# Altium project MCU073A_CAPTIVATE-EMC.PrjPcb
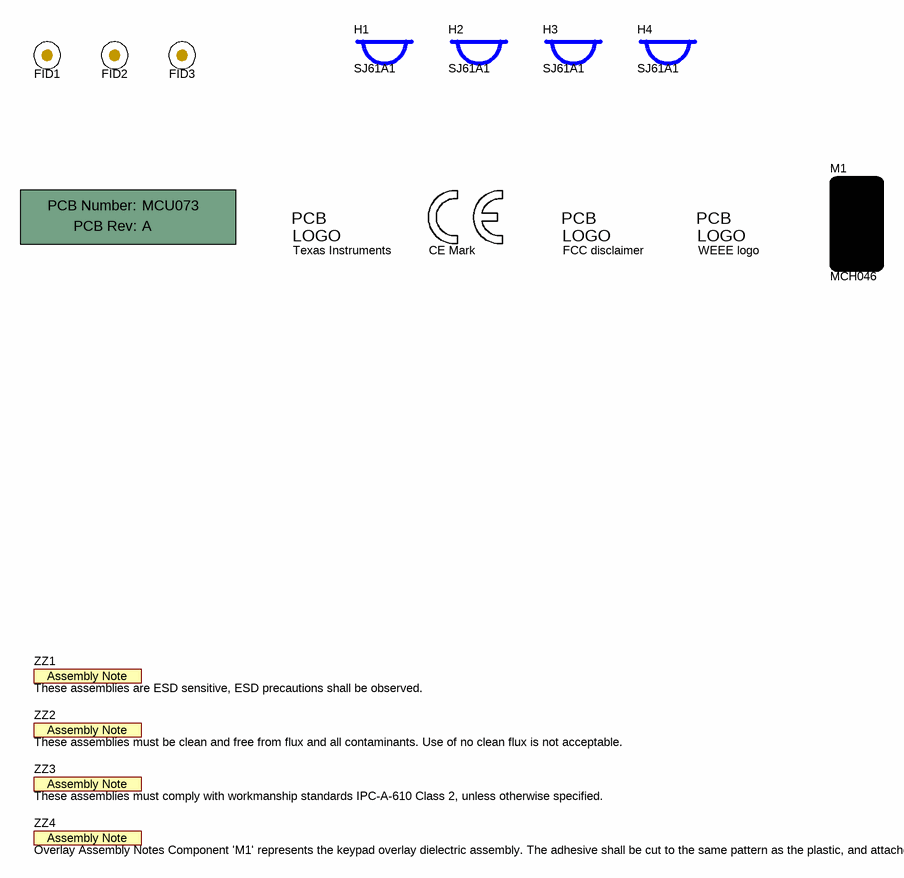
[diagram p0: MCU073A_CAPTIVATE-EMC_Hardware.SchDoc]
CopyrightYear: 2019; PCB_Layout: Ling Zhu; PCB_Rev: A; PRJ_Customer: Public Release; PRJ_Engineer: Ling Zhu; PRJ_Number: MCU073; PRJ_Title: CAPTIVATE-EMC; SCH_Rev: A; TechSupport: http://www.ti.com/support; TID: N/A
3 sheets, 127 parts. Net scope: global (net labels, ports and power ports of the same name join across sheets).
Board file: MCU073A_CAPTIVATE-EMC.PcbDoc
Sheets:
  MCU073A_CAPTIVATE-EMC_Hardware.SchDoc
  MCU073A_CAPTIVATE-EMC_MCU.SchDoc
  MCU073A_CAPTIVATE-EMC_PowerSupply.SchDoc

## Sheet MCU073A_CAPTIVATE-EMC_Hardware.SchDoc: CAPTIVATE-EMC_Hardware
size 431 x 279 mm; Date: Not shown in title block; ApprovedBy: Not shown in title block; CheckedBy: Not shown in title block; Author: Not shown in title block; CompanyName: Not shown in title block; DrawnBy: Ling Zhu; Engineer: Not shown in title block; Organization: Not shown in title block; Address1: Not shown in title block; Address2: Not shown in title block; Address3: Not shown in title block; Address4: Not shown in title block; DocumentNumber: 3; Revision: Use project parameter SCH_Rev; SheetNumber: 3; SheetTotal: 3; PageSetup: Record=PageOptions¦CenterHorizontal=True¦CenterVertical=True¦PrintScale=1.00¦XCorrection=1.00¦YCorrection=1.00¦PrintKind=0¦BorderSize=5000000¦LeftOffset=0¦BottomOffset=0¦Orientation=2¦PaperLength=1000¦PaperWidth=1000¦Scale=100¦PaperSource=15¦PrintQuality=600¦MediaType=1¦DitherType=10¦PaperKind=Letter¦PrintScaleMode=1

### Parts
!PCB1  Printed Circuit Board  (value not drawn)  (mechanical)
FID1  Fiducial  [Fiducial10-20]  (value not drawn)
FID2  Fiducial  [Fiducial10-20]  (value not drawn)
FID3  Fiducial  [Fiducial10-20]  (value not drawn)
H1  SJ61A1  [Bumpon_SJ61A1]
H2  SJ61A1  [Bumpon_SJ61A1]
H3  SJ61A1  [Bumpon_SJ61A1]
H4  SJ61A1  [Bumpon_SJ61A1]
Logo1  CE Mark  [CE_Mark_5mm]  (no BOM)
Logo2  Texas Instruments  [TI_Stacked_Overlay_Small]  (no BOM)
Logo3  FCC disclaimer  [FCC_disclaimer]  (no BOM)
Logo4  WEEE logo  [WEEE_Minimum]  (no BOM)
M1  MCH046  [CAPTIVATE-EMC-OVERLAY-PMMA]
ZZ1  These assemblies are ESD sensitive, ESD precautions shall be observed.  [AssemblyNote]  (no BOM)
ZZ2  These assemblies must be clean and free from flux and all contaminants. Use of no clean flux is not acceptable.  [AssemblyNote]  (no BOM)
ZZ3  These assemblies must comply with workmanship standards IPC-A-610 Class 2, unless otherwise specified.  [AssemblyNote]  (no BOM)
ZZ4  Overlay Assembly Notes / Component 'M1' represents the keypad overlay dielectric assembly. / The adhesive shall be cut to the same pattern as the plastic, and attached to the back of the plastic.  Then, the overlay plastic shall be bonded to the top layer of the PCB.  [AssemblyNote]  (no BOM)

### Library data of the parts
!PCB1 = CMP-0003618-2: Manufacturer: Any; PartNumber: MCU073
FID1-FID3 = CMP-0077181-1: Fiducial mark.  There is nothing to buy or mount.
H1-H4 = CMP-0003621-1: Bumpon, Cylindrical, 0.312 X 0.200, Black; Manufacturer: 3M
Logo1 = CMP-0074844-1: SymbolCreator: a0412235
Logo2 = CMP-0074838-1: Texas Instrument Corporate Signature; SymbolCreator: a0412235; Lib Reference: TI_Logo; Library Reference: Logo
Logo3 = CMP-0074847-1: FCC_disclaimer; Library Reference: Logo
Logo4 = CMP-0074769-1
M1 = CAPTIVATE-EMC-OVERLAY-PMMA: CAPTIVATE-EMC Overlay Plastic; Manufacturer: ANY; SymbolCreator: a0222632; CompType: Mechanical; U/M: EA, IN, or GM
ZZ1 = CMP-0077236-1
ZZ2 = CMP-0077237-1
ZZ3 ZZ4 = CMP-0077238-1

## Sheet MCU073A_CAPTIVATE-EMC_MCU.SchDoc: CAPTIVATE-EMC_MCU
size 431 x 279 mm; Date: Not shown in title block; ApprovedBy: Not shown in title block; CheckedBy: Not shown in title block; Author: Not shown in title block; CompanyName: Not shown in title block; DrawnBy: Ling Zhu; Engineer: Not shown in title block; Organization: Not shown in title block; Address1: Not shown in title block; Address2: Not shown in title block; Address3: Not shown in title block; Address4: Not shown in title block; DocumentNumber: 1; Revision: Use project parameter SCH_Rev; SheetNumber: 1; SheetTotal: 3; PageSetup: Record=PageOptions¦CenterHorizontal=True¦CenterVertical=True¦PrintScale=1.00¦XCorrection=1.00¦YCorrection=1.00¦PrintKind=0¦BorderSize=5000000¦LeftOffset=0¦BottomOffset=0¦Orientation=2¦PaperLength=1000¦PaperWidth=1000¦Scale=100¦PaperSource=15¦PrintQuality=600¦MediaType=1¦DitherType=10¦PaperKind=Letter¦PrintScaleMode=1
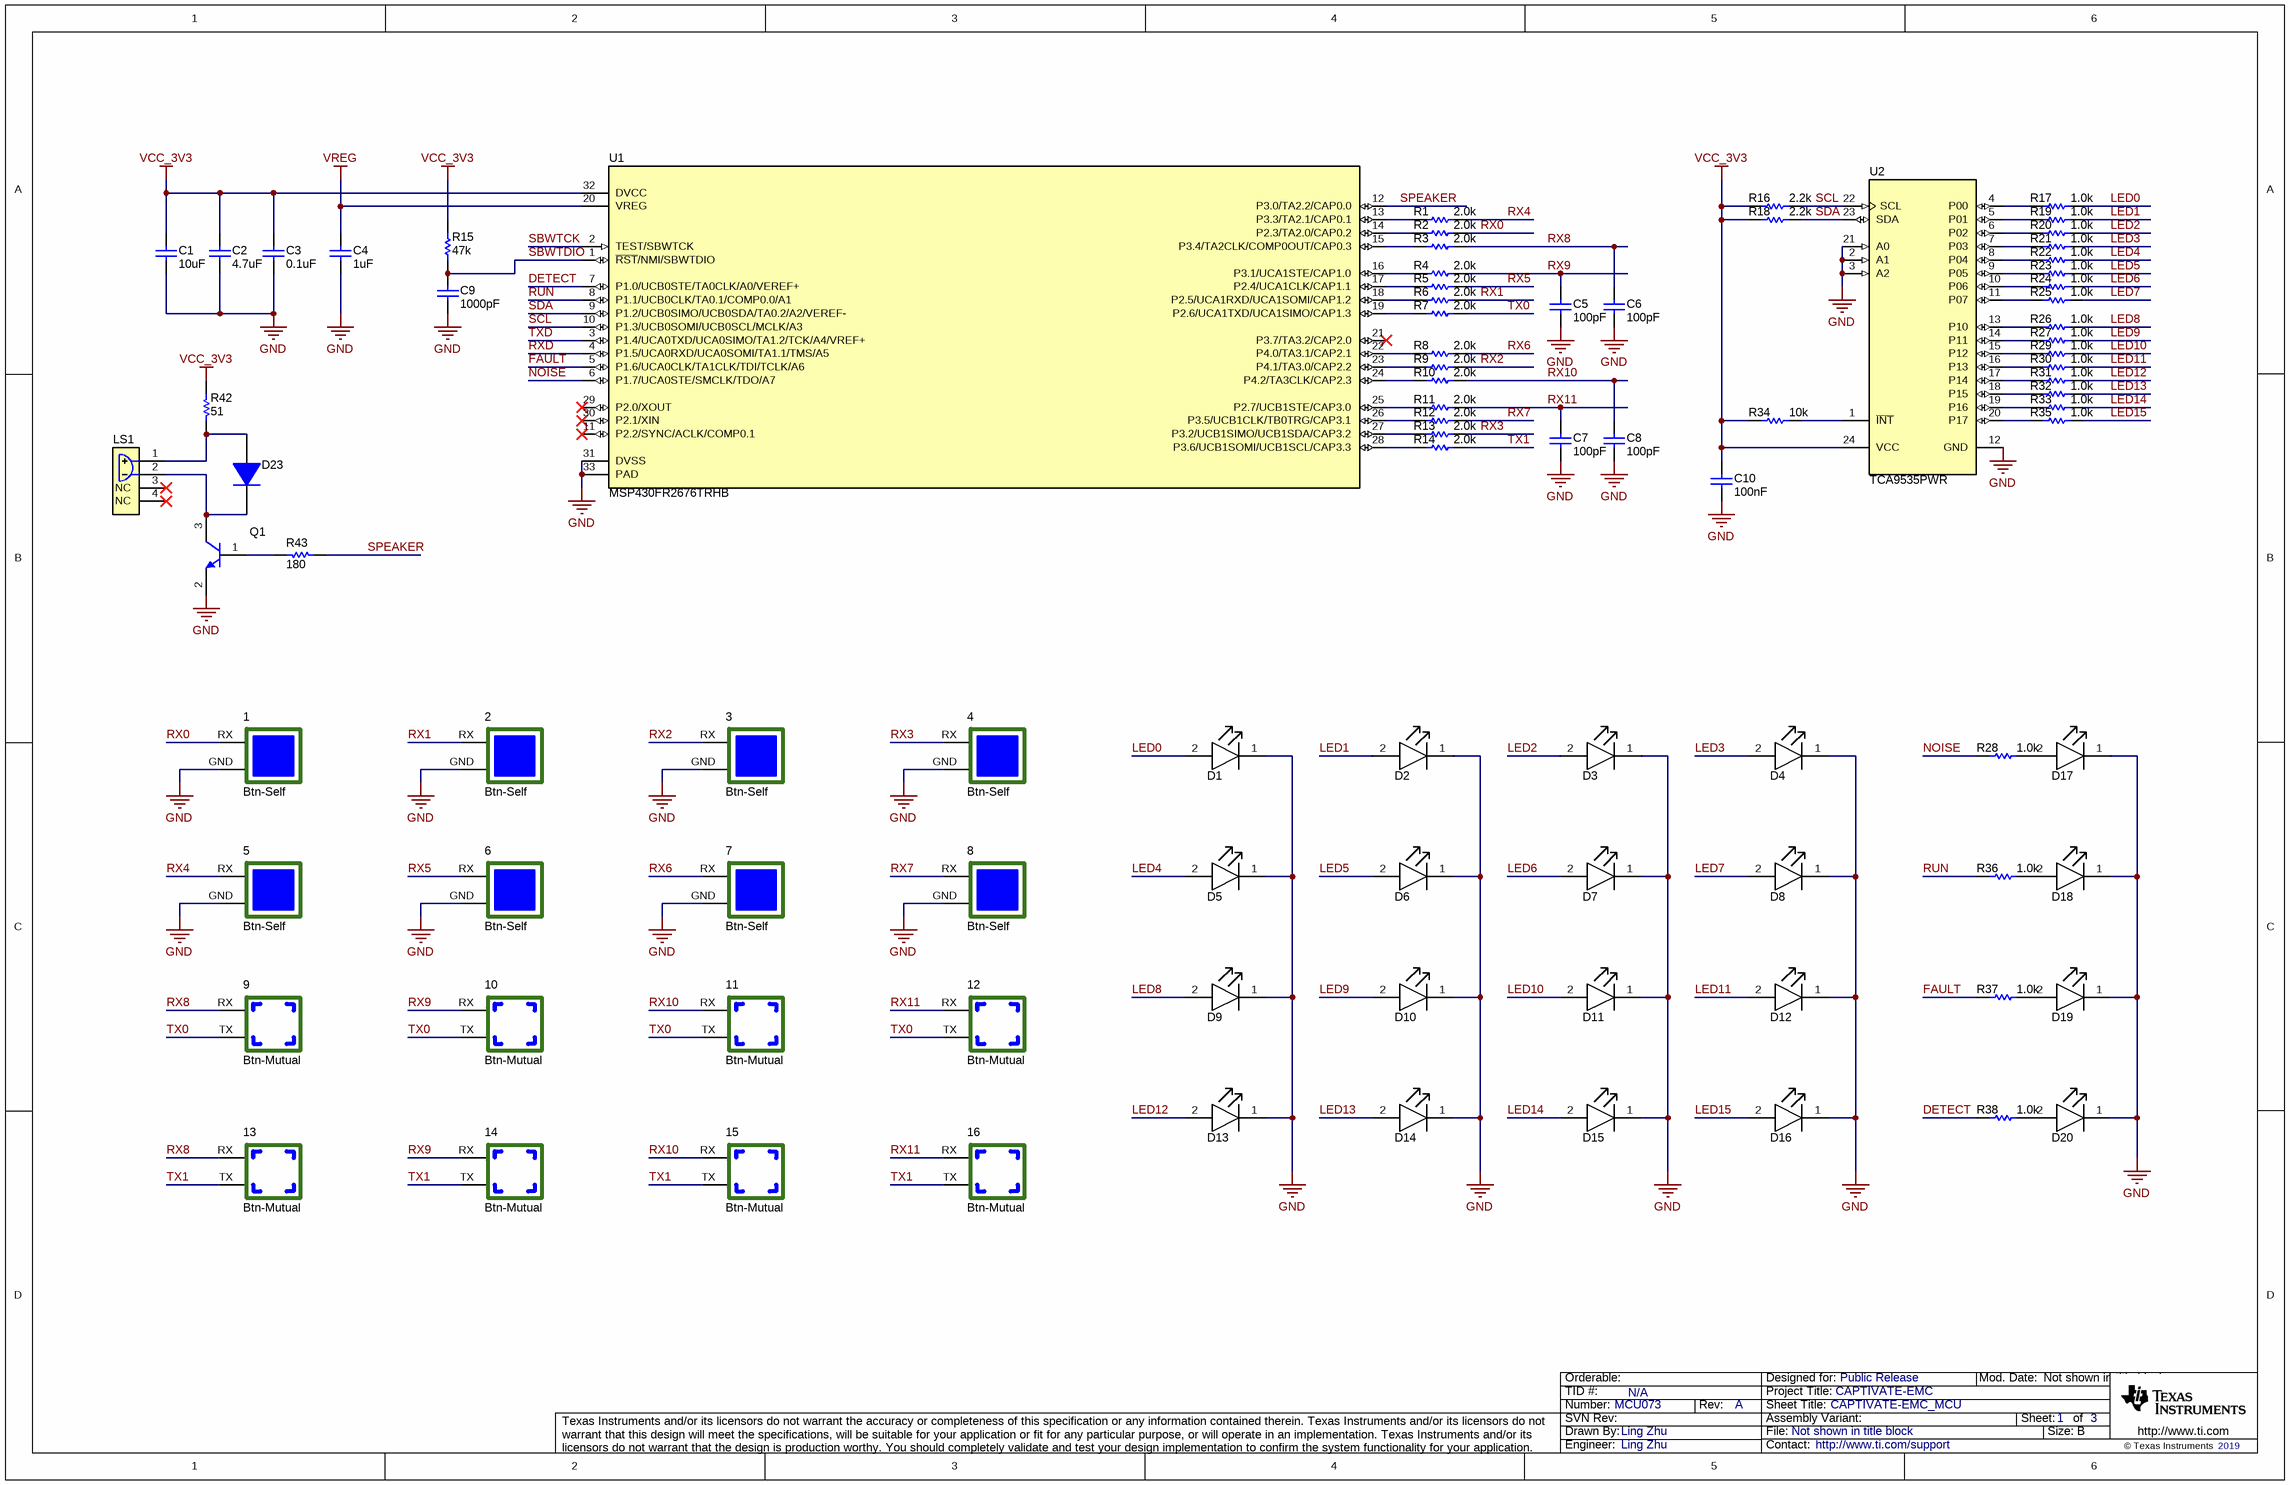
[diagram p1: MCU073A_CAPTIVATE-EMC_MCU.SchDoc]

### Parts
1  Btn-Self  [btn-self]  (no BOM)
2  Btn-Self  [btn-self]  (no BOM)
3  Btn-Self  [btn-self]  (no BOM)
4  Btn-Self  [btn-self]  (no BOM)
5  Btn-Self  [btn-self]  (no BOM)
6  Btn-Self  [btn-self]  (no BOM)
7  Btn-Self  [btn-self]  (no BOM)
8  Btn-Self  [btn-self]  (no BOM)
9  Btn-Mutual  [btn-mutual]  (no BOM)
10  Btn-Mutual  [btn-mutual]  (no BOM)
11  Btn-Mutual  [btn-mutual]  (no BOM)
12  Btn-Mutual  [btn-mutual]  (no BOM)
13  Btn-Mutual  [btn-mutual]  (no BOM)
14  Btn-Mutual  [btn-mutual]  (no BOM)
15  Btn-Mutual  [btn-mutual]  (no BOM)
16  Btn-Mutual  [btn-mutual]  (no BOM)
C1  ValueDisplayed: 10uF  [0603]  (hidden comment: GRM188R60J106ME47D)
C2  ValueDisplayed: 4.7uF  [0402]  (hidden comment: C1005X5R0J475M050BC)
C3  ValueDisplayed: 0.1uF  [0402]  (hidden comment: GCM155R71C104KA55D)
C4  ValueDisplayed: 1uF  [0402]  (hidden comment: GRM155R70J105KA12D)
C5  ValueDisplayed: 100pF  [0402]  (hidden comment: C0402C101J3GACTU)
C6  ValueDisplayed: 100pF  [0402]  (hidden comment: C0402C101J3GACTU)
C7  ValueDisplayed: 100pF  [0402]  (hidden comment: C0402C101J3GACTU)
C8  ValueDisplayed: 100pF  [0402]  (hidden comment: C0402C101J3GACTU)
C9  ValueDisplayed: 1000pF  [0402]  (hidden comment: GCM155R71H102KA37D)
C10  Cap_F: 100nF  [0603]  (hidden comment: GCJ188R72A104KA01D)
D1  AM2520SRC09  [FP-AM2520SRC09_SMD2-MFG]  (value not drawn)
D2  AM2520SRC09  [FP-AM2520SRC09_SMD2-MFG]  (value not drawn)
D3  AM2520SRC09  [FP-AM2520SRC09_SMD2-MFG]  (value not drawn)
D4  AM2520SRC09  [FP-AM2520SRC09_SMD2-MFG]  (value not drawn)
D5  AM2520SRC09  [FP-AM2520SRC09_SMD2-MFG]  (value not drawn)
D6  AM2520SRC09  [FP-AM2520SRC09_SMD2-MFG]  (value not drawn)
D7  AM2520SRC09  [FP-AM2520SRC09_SMD2-MFG]  (value not drawn)
D8  AM2520SRC09  [FP-AM2520SRC09_SMD2-MFG]  (value not drawn)
D9  AM2520SRC09  [FP-AM2520SRC09_SMD2-MFG]  (value not drawn)
D10  AM2520SRC09  [FP-AM2520SRC09_SMD2-MFG]  (value not drawn)
D11  AM2520SRC09  [FP-AM2520SRC09_SMD2-MFG]  (value not drawn)
D12  AM2520SRC09  [FP-AM2520SRC09_SMD2-MFG]  (value not drawn)
D13  AM2520SRC09  [FP-AM2520SRC09_SMD2-MFG]  (value not drawn)
D14  AM2520SRC09  [FP-AM2520SRC09_SMD2-MFG]  (value not drawn)
D15  AM2520SRC09  [FP-AM2520SRC09_SMD2-MFG]  (value not drawn)
D16  AM2520SRC09  [FP-AM2520SRC09_SMD2-MFG]  (value not drawn)
D17  AM2520SECK09  [FP-AM2520SECK09_SMT_LED_2MM5_2MM0-MFG]  (value not drawn)
D18  AM2520ZGC09  [FP-AM2520ZGC09_SMD2-0]  (value not drawn)
D19  AM2520SRC09  [FP-AM2520SRC09_SMD2-MFG]  (value not drawn)
D20  AM2520QBC/D09  [FP-AM2520QBC_D09]  (value not drawn)
D23  1N4148WX-TP  [SOD-323]  (value not drawn)
LS1  ST-03BL  [Soberton_ST-03BL]  (value not drawn)
Q1  MMBT3904-7-F  [SOT-23]  (value not drawn)
R1  ValueDisplayed: 2.0k  [0402]  (hidden comment: CRCW04022K00JNED)
R2  ValueDisplayed: 2.0k  [0402]  (hidden comment: CRCW04022K00JNED)
R3  ValueDisplayed: 2.0k  [0402]  (hidden comment: CRCW04022K00JNED)
R4  ValueDisplayed: 2.0k  [0402]  (hidden comment: CRCW04022K00JNED)
R5  ValueDisplayed: 2.0k  [0402]  (hidden comment: CRCW04022K00JNED)
R6  ValueDisplayed: 2.0k  [0402]  (hidden comment: CRCW04022K00JNED)
R7  ValueDisplayed: 2.0k  [0402]  (hidden comment: CRCW04022K00JNED)
R8  ValueDisplayed: 2.0k  [0402]  (hidden comment: CRCW04022K00JNED)
R9  ValueDisplayed: 2.0k  [0402]  (hidden comment: CRCW04022K00JNED)
R10  ValueDisplayed: 2.0k  [0402]  (hidden comment: CRCW04022K00JNED)
R11  ValueDisplayed: 2.0k  [0402]  (hidden comment: CRCW04022K00JNED)
R12  ValueDisplayed: 2.0k  [0402]  (hidden comment: CRCW04022K00JNED)
R13  ValueDisplayed: 2.0k  [0402]  (hidden comment: CRCW04022K00JNED)
R14  ValueDisplayed: 2.0k  [0402]  (hidden comment: CRCW04022K00JNED)
R15  ValueDisplayed: 47k  [0402]  (hidden comment: CRCW040247K0JNED)
R16  ValueDisplayed: 2.2k  [0402]  (hidden comment: CRCW04022K20JNED)
R17  ValueDisplayed: 1.0k  [0402]  (hidden comment: CRCW04021K00JNED)
R18  ValueDisplayed: 2.2k  [0402]  (hidden comment: CRCW04022K20JNED)
R19  ValueDisplayed: 1.0k  [0402]  (hidden comment: CRCW04021K00JNED)
R20  ValueDisplayed: 1.0k  [0402]  (hidden comment: CRCW04021K00JNED)
R21  ValueDisplayed: 1.0k  [0402]  (hidden comment: CRCW04021K00JNED)
R22  ValueDisplayed: 1.0k  [0402]  (hidden comment: CRCW04021K00JNED)
R23  ValueDisplayed: 1.0k  [0402]  (hidden comment: CRCW04021K00JNED)
R24  ValueDisplayed: 1.0k  [0402]  (hidden comment: CRCW04021K00JNED)
R25  ValueDisplayed: 1.0k  [0402]  (hidden comment: CRCW04021K00JNED)
R26  ValueDisplayed: 1.0k  [0402]  (hidden comment: CRCW04021K00JNED)
R27  ValueDisplayed: 1.0k  [0402]  (hidden comment: CRCW04021K00JNED)
R28  ValueDisplayed: 1.0k  [0402]  (hidden comment: CRCW04021K00JNED)
R29  ValueDisplayed: 1.0k  [0402]  (hidden comment: CRCW04021K00JNED)
R30  ValueDisplayed: 1.0k  [0402]  (hidden comment: CRCW04021K00JNED)
R31  ValueDisplayed: 1.0k  [0402]  (hidden comment: CRCW04021K00JNED)
R32  ValueDisplayed: 1.0k  [0402]  (hidden comment: CRCW04021K00JNED)
R33  ValueDisplayed: 1.0k  [0402]  (hidden comment: CRCW04021K00JNED)
R34  ValueDisplayed: 10k  [0603]  (hidden comment: RC1608J103CS)
R35  ValueDisplayed: 1.0k  [0402]  (hidden comment: CRCW04021K00JNED)
R36  ValueDisplayed: 1.0k  [0402]  (hidden comment: CRCW04021K00JNED)
R37  ValueDisplayed: 1.0k  [0402]  (hidden comment: CRCW04021K00JNED)
R38  ValueDisplayed: 1.0k  [0402]  (hidden comment: CRCW04021K00JNED)
R42  ValueDisplayed: 51  [0402]  (hidden comment: CRCW040251R0JNED)
R43  ValueDisplayed: 180  [0402]  (hidden comment: CRCW0402180RJNED)
U1  MSP430FR2676TRHB  [RHB0032E]
U2  TCA9535PWR  [PW0024A_N]

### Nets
GND: 1.GND 2.GND 3.GND 4.GND 5.GND 6.GND 7.GND 8.GND C1.2 C2.2 C3.1 C4.2 C5.1 C6.1 C7.1 C8.1 C9.1 C10.2 D1.1(CATHODE) D2.1(CATHODE) D3.1(CATHODE) D4.1(CATHODE) D5.1(CATHODE) D6.1(CATHODE) D7.1(CATHODE) D8.1(CATHODE) D9.1(CATHODE) D10.1(CATHODE) D11.1(CATHODE) D12.1(CATHODE) D13.1(CATHODE) D14.1(CATHODE) D15.1(CATHODE) D16.1(CATHODE) D17.1(CATHODE) D18.1(CATHODE) D19.1(CATHODE) D20.1(CATHODE) Q1.2(E) U1.31(DVSS) U1.33(PAD) U2.2(A1) U2.3(A2) U2.12(GND) U2.21(A0)
VCC_3V3: C1.1 C2.1 C3.2 C10.1 R15.2 R16.2 R18.2 R34.1 R42.2 U1.32(DVCC) U2.24(VCC)
VREG: C4.1 U1.20(VREG)
DETECT: R38.1 U1.7(P1.0/UCB0STE/TA0CLK/A0/VEREF+)
FAULT: R37.1 U1.5(P1.6/UCA0CLK/TA1CLK/TDI/TCLK/A6)
LED0: D1.2(ANODE) R17.2
LED1: D2.2(ANODE) R19.2
LED2: D3.2(ANODE) R20.2
LED3: D4.2(ANODE) R21.2
LED4: D5.2(ANODE) R22.2
LED5: D6.2(ANODE) R23.2
LED6: D7.2(ANODE) R24.2
LED7: D8.2(ANODE) R25.2
LED8: D9.2(ANODE) R26.2
LED9: D10.2(ANODE) R27.2
LED10: D11.2(ANODE) R29.2
LED11: D12.2(ANODE) R30.2
LED12: D13.2(ANODE) R31.2
LED13: D14.2(ANODE) R32.2
LED14: D15.2(ANODE) R33.2
LED15: D16.2(ANODE) R35.2
NOISE: R28.1 U1.6(P1.7/UCA0STE/SMCLK/TDO/A7)
RUN: R36.1 U1.8(P1.1/UCB0CLK/TA0.1/COMP0.0/A1)
RX0: 1.RX R2.2
RX1: 2.RX R6.2
RX2: 3.RX R9.2
RX3: 4.RX R13.2
RX4: 5.RX R1.2
RX5: 6.RX R5.2
RX6: 7.RX R8.2
RX7: 8.RX R12.2
RX8: 9.RX 13.RX C6.2 R3.2
RX9: 10.RX 14.RX C5.2 R4.2
RX10: 11.RX 15.RX C8.2 R10.2
RX11: 12.RX 16.RX C7.2 R11.2
RXD: U1.4(P1.5/UCA0RXD/UCA0SOMI/TA1.1/TMS/A5)
SBWTCK: U1.2(TEST/SBWTCK)
SBWTDIO: C9.2 R15.1 U1.1(~{RST}/NMI/SBWTDIO)
SCL: R16.1 U1.10(P1.3/UCB0SOMI/UCB0SCL/MCLK/A3) U2.22(SCL)
SDA: R18.1 U1.9(P1.2/UCB0SIMO/UCB0SDA/TA0.2/A2/VEREF-) U2.23(SDA)
SPEAKER: R43.1 U1.12(P3.0/TA2.2/CAP0.0)
TX0: 9.TX 10.TX 11.TX 12.TX R7.2
TX1: 13.TX 14.TX 15.TX 16.TX R14.2
TXD: U1.3(P1.4/UCA0TXD/UCA0SIMO/TA1.2/TCK/A4/VREF+)
NetD17_2: D17.2(ANODE) R28.2
NetD18_2: D18.2(ANODE) R36.2
NetD19_2: D19.2(ANODE) R37.2
NetD20_2: D20.2(ANODE) R38.2
NetD23_1: D23.1(K) LS1.2(-) Q1.3(C)
NetD23_2: D23.2(A) LS1.1(+) R42.1
NetQ1_1: Q1.1(B) R43.2
NetR1_1: R1.1 U1.13(P3.3/TA2.1/CAP0.1)
NetR2_1: R2.1 U1.14(P2.3/TA2.0/CAP0.2)
NetR3_1: R3.1 U1.15(P3.4/TA2CLK/COMP0OUT/CAP0.3)
NetR4_1: R4.1 U1.16(P3.1/UCA1STE/CAP1.0)
NetR5_1: R5.1 U1.17(P2.4/UCA1CLK/CAP1.1)
NetR6_1: R6.1 U1.18(P2.5/UCA1RXD/UCA1SOMI/CAP1.2)
NetR7_1: R7.1 U1.19(P2.6/UCA1TXD/UCA1SIMO/CAP1.3)
NetR8_1: R8.1 U1.22(P4.0/TA3.1/CAP2.1)
NetR9_1: R9.1 U1.23(P4.1/TA3.0/CAP2.2)
NetR10_1: R10.1 U1.24(P4.2/TA3CLK/CAP2.3)
NetR11_1: R11.1 U1.25(P2.7/UCB1STE/CAP3.0)
NetR12_1: R12.1 U1.26(P3.5/UCB1CLK/TB0TRG/CAP3.1)
NetR13_1: R13.1 U1.27(P3.2/UCB1SIMO/UCB1SDA/CAP3.2)
NetR14_1: R14.1 U1.28(P3.6/UCB1SOMI/UCB1SCL/CAP3.3)
NetR17_1: R17.1 U2.4(P00)
NetR19_1: R19.1 U2.5(P01)
NetR20_1: R20.1 U2.6(P02)
NetR21_1: R21.1 U2.7(P03)
NetR22_1: R22.1 U2.8(P04)
NetR23_1: R23.1 U2.9(P05)
NetR24_1: R24.1 U2.10(P06)
NetR25_1: R25.1 U2.11(P07)
NetR26_1: R26.1 U2.13(P10)
NetR27_1: R27.1 U2.14(P11)
NetR29_1: R29.1 U2.15(P12)
NetR30_1: R30.1 U2.16(P13)
NetR31_1: R31.1 U2.17(P14)
NetR32_1: R32.1 U2.18(P15)
NetR33_1: R33.1 U2.19(P16)
NetR34_2: R34.2 U2.1(~{INT})
NetR35_1: R35.1 U2.20(P17)

Not connected (* = marked no-connect by the designer): LS1 3(NC)* 4(NC)*; U1 11(P2.2/SYNC/ACLK/COMP0.1)* 21(P3.7/TA3.2/CAP2.0)* 29(P2.0/XOUT)* 30(P2.1/XIN)*

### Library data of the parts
1-8 = btn-self: Capacitive Button, Self Capacitance, 2-Layer, EMC; SymbolCreator: a0222632; CompType: Electrode; U/M: EA, IN, or GM
9-16 = btn-mutual: Capacitive Button, Mutual Capacitance, 2-layer; SymbolCreator: a0222632; CompType: Electrode; U/M: EA, IN, or GM
C1 = CMP-0007303-5: CAP, CERM, 10 uF, 6.3 V, +/- 20%, X5R, 0603; Manufacturer: MuRata; TaMin_C: -55°C; ESR_ohm: 9m; Polarized: N; SizeAreaWB_mm2: 4.68; Value1: 0.009 ohm; U/M: EA; Value: 10uF; TaMax_C: 125°C; SizeZ_mm: 1; SizeX_mm: 1.6; SizeY_mm: 0.8; Value2: 6.3V; SizeArea_mm2: 1.28; Cap_F: 10µF; IRMS_A: 2.74A; AEC Category: Q200
C2 = CMP-0006258-2: CAP, CERM, 4.7 uF, 6.3 V, +/- 20%, X5R, 0402; Manufacturer: TDK; TaMin_C: -55°C; Polarized: N; SizeAreaWB_mm2: 3; Value1: Unknown; U/M: EA; Value: 4.7uF; TaMax_C: 85°C; SizeZ_mm: 0.6; SizeX_mm: 1; SizeY_mm: 0.5; Value2: 6.3V; Cap_F: 4.7µF; AEC Category: Q200
C3 = CMP-0006351-2: CAP, CERM, 0.1 uF, 16 V, +/- 10%, X7R, 0402; Manufacturer: MuRata; TaMin_C: -55°C; Polarized: N; SizeAreaWB_mm2: 3; Value1: Unknown; U/M: EA; Value: 0.1uF; TaMax_C: 125°C; SizeZ_mm: 0.6; SizeX_mm: 1; SizeY_mm: 0.5; Value2: 16V; Cap_F: 100nF; AEC Category: Q200
C4 = CMP-0064947-2: CAP, CERM, 1 uF, 6.3 V,+/- 10%, X7R, 0402; Manufacturer: MuRata; TaMin_C: -55°C; Polarized: N; SizeAreaWB_mm2: 3; Value1: Unknown; U/M: EA; Value: 1uF; TaMax_C: 125°C; SizeZ_mm: 0.6; SizeX_mm: 1; SizeY_mm: 0.5; Value2: 6.3V; Cap_F: 1µF; AEC Category: Q200
C5-C8 = CMP-0006233-2: CAP, CERM, 100 pF, 25 V, +/- 5%, C0G/NP0, 0402; Manufacturer: Kemet; TaMin_C: -55°C; Polarized: N; SizeAreaWB_mm2: 3; Value1: Unknown; U/M: EA; Value: 100pF; TaMax_C: 125°C; SizeZ_mm: 0.6; SizeX_mm: 1; SizeY_mm: 0.5; Value2: 25V; AEC Category: Q200
C9 = CMP-0006354-2: CAP, CERM, 1000 pF, 50 V, +/- 10%, X7R, AEC-Q200 Grade 1, 0402; Manufacturer: MuRata; TaMin_C: -55°C; Polarized: N; SizeAreaWB_mm2: 3; Value1: Unknown; U/M: EA; Value: 1000pF; TaMax_C: 125°C; SizeZ_mm: 0.6; SizeX_mm: 1; SizeY_mm: 0.5; Value2: 50V; AEC Qualified: Y; Cap_F: 1nF; AEC Category: Q200
C10 = CMP-0064935-4: CAP, CERM, 0.1 uF, 100 V,+/- 10%, X7R, AEC-Q200 Grade 1, 0603; Manufacturer: MuRata; TaMin_C: -55°C; Polarized: N; SizeAreaWB_mm2: 4.68; Value1: Unknown; U/M: EA; Value: 0.1uF; TaMax_C: 125°C; SizeZ_mm: 1; SizeX_mm: 1.6; SizeY_mm: 0.8; Value2: 100V; SizeArea_mm2: 1.28; AEC Qualified: Y; AEC Category: Q200
D1-D16 D19 = CMP-0086387-1: Red 2.5 x 2 x 2.8 mm 20° Clear 800 mcd 1.85 V Subminiature Solid State LED SMT; Manufacturer: Kingbright Company LLC; SizeZ_mm: 1.7mm; LambdaD: 640nm; Vr_V: 5V; Symbol Name: SYM-AM2520SRC09; Power_TotalModule: 75mW; Vf_V: 1.85V; LambdaP: 655nm
D17 = CMP-0086381-1: SUBMINIATURE SOLID STATE LAMP, Super Bright Orange, 20º, 2700mcd Clear; Manufacturer: Kingbright; Vf_V: 2.1V; Vr_V: 5V; Symbol Name: SYM-AM2520SECK09; Tjmax_C: 115°C; Angle: 20°; LambdaD: 605nm; SizeZ_mm: 1.5mm; LambdaP: 610nm; Power_TotalModule: 75mW
D18 = CMP-0087006-1: Green 2.5 x 2 x 2.8 mm 20° Clear 2700 mcd 3.3 V Subminiature Solid State LED SMT; Manufacturer: Kingbright; Power_TotalModule: 102.5mW; LambdaD: 525nm; SizeZ_mm: 1.7mm; Symbol Name: SYM-AM2520ZGC09; LambdaP: 515nm; Vf_V: 3.3V; Vr_V: 5V; Tjmax_C: 115°C
D20 = CMP-0077505-2: LED Blue 465nm - Discrete 3.3V 2-SMD, Z-Bend; Manufacturer: Kingbright; Power_TotalModule: 120mW; LambdaP: 460nm; SizeZ_mm: 1.7mm; Angle: 20°; Symbol Name: SYM-AM2520QBC/D09; Tjmax_C: 115°C; Vr_V: 5V
D23 = CMP-0082069-2: Diode, Switching, 75 V, 0.15 A, SOD-323; Manufacturer: Micro Commercial Components; AEC Category: Q101; AEC Qualified: N; Value1: 0.15A; SizeX_mm: 2.7; Vr_V: 75V; Vf_V: 1V; SizeZ_mm: 1; SizeY_mm: 1.35; Value: 75V; SizeAreaWB_mm2: 8.695; TJmax_C: 150°C; RJC_CperW: 625; Io_A: 1.5dA; SizeArea_mm2: 3.645
LS1 = CMP-0078858-2: Magnetic Transducer, SMD; Manufacturer: Sobertron; SizeAreaWB_mm2: 110.25; SizeArea_mm2: 72.25; SizeZ_mm: 3.2; SizeX_mm: 8.5
Q1 = CMP-0000387-2: Transistor, NPN, 40 V, 0.2 A, SOT-23; Manufacturer: Diodes Inc.; TaMax_C: 150°C; Value2: 400; Value1: 0.2 A; Vcesat1_V: 200mV; SizeX_mm: 2.5; SizeY_mm: 3; TaMin_C: -55°C; IcRated_A: 200mA; CompType: BJT; SizeZ_mm: 1.1; Value: 40 V; SizeArea_mm2: 7.5; NPN: 1; Vceo_V: 40V; PNP: 0; AEC Category: Q101; SizeAreaWB_mm2: 14; U/M: EA
R1-R14 = CMP-0026889-5: RES, 2.0 k, 5%, 0.063 W, AEC-Q200 Grade 0, 0402; Manufacturer: Vishay-Dale; Power_W: 63mW; TempCo: 200 ppm/C; Value_Code: 2k00; Value: 2.0k; EIA_Code: E24; Res_ohm: 2k; SizeX_mm: 1; SizeY_mm: 0.5; SizeZ_mm: 0.6; Value2: 0.063W; AEC Qualified: Y; VDC_V: 50V; AEC Category: Q200; AEC Grade: 0
R15 = CMP-0026935-3: RES, 47 k, 5%, 0.063 W, AEC-Q200 Grade 0, 0402; Manufacturer: Vishay-Dale; Power_W: 63mW; TempCo: 200 ppm/C; Value_Code: 47k0; Value: 47k; EIA_Code: E24; SizeX_mm: 1; SizeY_mm: 0.5; SizeZ_mm: 0.6; Value2: 0.063W; AEC Qualified: Y; VDC_V: 50V; AEC Category: Q200; AEC Grade: 0
R16 R18 = CMP-0026890-5: RES, 2.2 k, 5%, 0.063 W, AEC-Q200 Grade 0, 0402; Manufacturer: Vishay-Dale; Power_W: 63mW; TempCo: 200 ppm/C; Value_Code: 2k20; Value: 2.2k; EIA_Code: E24; SizeX_mm: 1; SizeY_mm: 0.5; SizeZ_mm: 0.6; Value2: 0.063W; AEC Qualified: Y; VDC_V: 50V; AEC Category: Q200; AEC Grade: 0
R17 R19-R33 R35-R38 = CMP-0026852-3: RES, 1.0 k, 5%, 0.063 W, AEC-Q200 Grade 0, 0402; Manufacturer: Vishay-Dale; Power_W: 63mW; TempCo: 200 ppm/C; Value_Code: 1k00; Value: 1.0k; EIA_Code: E24; Res_ohm: 1k; SizeX_mm: 1; SizeY_mm: 0.5; SizeZ_mm: 0.6; Value2: 0.063W; AEC Qualified: Y; VDC_V: 50V; AEC Category: Q200; AEC Grade: 0
R34 = CMP-0025945-3: RES, 10 k, 5%, 0.1 W, 0603; Manufacturer: Samsung Electro-Mechanics; Power_W: 100mW; TempCo: 100 ppm/C; Value_Code: 10k0; U/M: EA; Value: 10k; EIA_Code: E24; SizeX_mm: 1.6; SizeY_mm: 0.8; SizeZ_mm: 1; Value2: 0.1W; SizeArea_mm2: 1.28; AEC Qualified: N; VDC_V: 31V; AEC Category: Q200
R42 = CMP-0026946-3: RES, 51, 5%, 0.063 W, AEC-Q200 Grade 0, 0402; Manufacturer: Vishay-Dale; Power_W: 63mW; TempCo: 200 ppm/C; Value_Code: 51R0; Value: 51; EIA_Code: E24; SizeX_mm: 1; SizeY_mm: 0.5; SizeZ_mm: 0.6; Value2: 0.063W; AEC Qualified: Y; VDC_V: 50V; AEC Category: Q200; AEC Grade: 0
R43 = CMP-0026849-3: RES, 180, 5%, 0.063 W, AEC-Q200 Grade 0, 0402; Manufacturer: Vishay-Dale; Power_W: 63mW; TempCo: 200 ppm/C; Value_Code: 180R; Value: 180; EIA_Code: E24; SizeX_mm: 1; SizeY_mm: 0.5; SizeZ_mm: 0.6; Value2: 0.063W; AEC Qualified: Y; VDC_V: 50V; AEC Category: Q200; AEC Grade: 0
U1 = CMP-0080656-1: Capacitive Touch Sensing Mixed-Signal Microcontroller, RHB0032E (VQFN-32); Manufacturer: Texas Instruments; SizeAreaWB_mm2: 49; SizeArea_mm2: 25; AEC Qualified: N; AEC Category: Q200; SizeZ_mm: 1; SizeY_mm: 5; CompType: IC
U2 = CMP-0043216-2: Remote 16-Bit I2C and SMBus, Low-Power I/O Expander With Interrupt Output and Config Registers, PW0024A (TSSOP-24); Manufacturer: Texas Instruments; SubFamily: I2C IO Expander; Vcc range(V): 1.65 to 5.5; Configuration Registers: Yes; Max Frequency(kHz): 400; Eco-Plan: Green (RoHS & no Sb/Br); # of I/Os: 16; I2C Address: 0100 xxx; Rating: Catalog; AEC Category: Q200; AEC Qualified: N; CompType: IC; SizeAreaWB_mm2: 82.32; SizeArea_mm2: 49.92; SizeX_mm: 6.4; SizeY_mm: 7.8; SizeZ_mm: 1.2

## Sheet MCU073A_CAPTIVATE-EMC_PowerSupply.SchDoc: CAPTIVATE-EMC_PowerSupply
size 431 x 279 mm; Date: Not shown in title block; ApprovedBy: Not shown in title block; CheckedBy: Not shown in title block; Author: Not shown in title block; CompanyName: Not shown in title block; DrawnBy: Ling Zhu; Engineer: Not shown in title block; Organization: Not shown in title block; Address1: Not shown in title block; Address2: Not shown in title block; Address3: Not shown in title block; Address4: Not shown in title block; DocumentNumber: 2; Revision: Use project parameter SCH_Rev; SheetNumber: 2; SheetTotal: 3; PageSetup: Record=PageOptions¦CenterHorizontal=True¦CenterVertical=True¦PrintScale=1.00¦XCorrection=1.00¦YCorrection=1.00¦PrintKind=0¦BorderSize=5000000¦LeftOffset=0¦BottomOffset=0¦Orientation=2¦PaperLength=1000¦PaperWidth=1000¦Scale=100¦PaperSource=15¦PrintQuality=600¦MediaType=1¦DitherType=10¦PaperKind=Letter¦PrintScaleMode=1
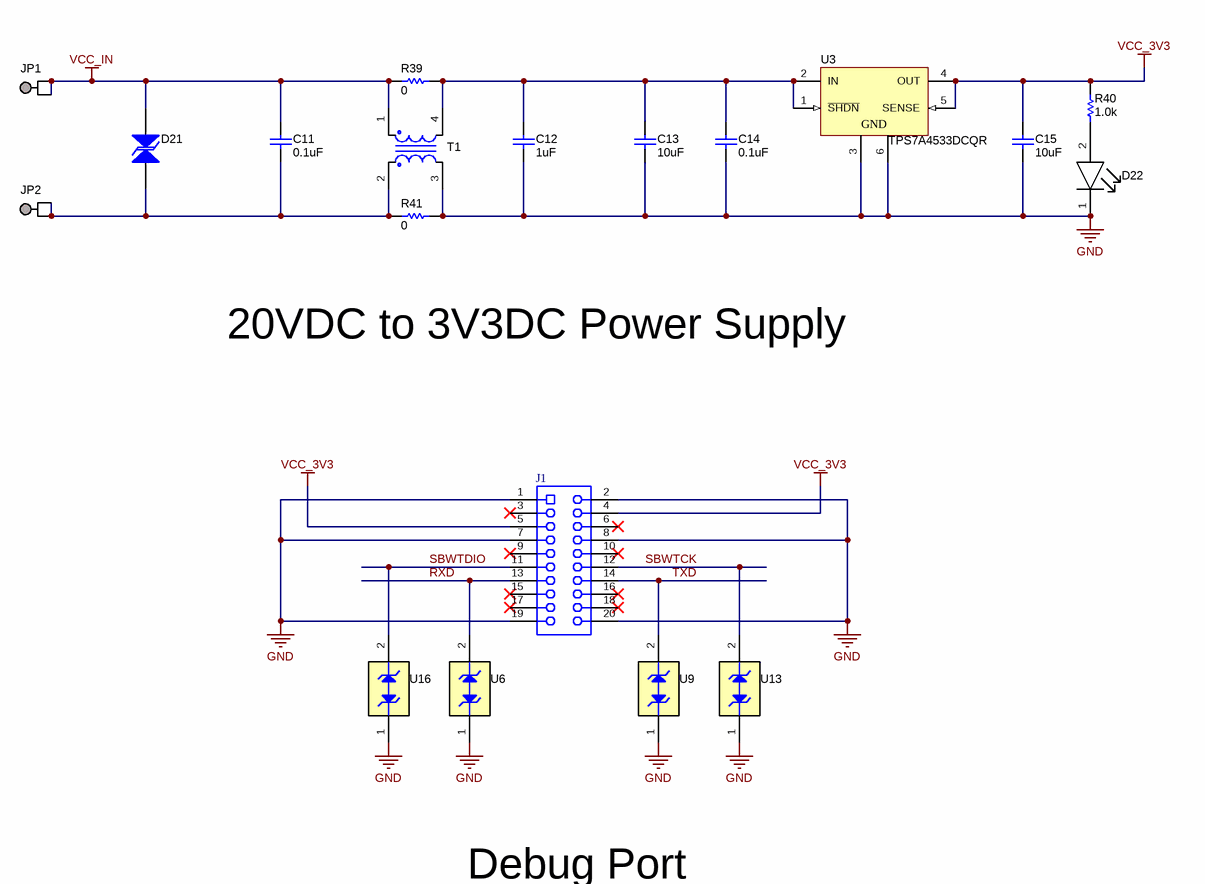
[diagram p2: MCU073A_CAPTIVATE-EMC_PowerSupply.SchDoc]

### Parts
C11  ValueDisplayed: 0.1uF  [1206]  (hidden comment: 12061C104MAT2A)
C12  ValueDisplayed: 1uF  [1206]  (hidden comment: 12063C105KAT2A)
C13  ValueDisplayed: 10uF  [0805_HV]  (hidden comment: CL21A106KAFN3NE)
C14  ValueDisplayed: 0.1uF  [0805_HV]  (hidden comment: 08053C104KAT2A)
C15  ValueDisplayed: 10uF  [0805_HV]  (hidden comment: CL21A106KAFN3NE)
D21  CDSOD323-T15SC  [SOD-323-Bi]  (value not drawn)
D22  AM2520SRC09  [FP-AM2520SRC09_SMD2-MFG]  (value not drawn)
J1  PPPC102LJBN-RC  [Sullins_xPxC102LJBN]  (value not drawn)
JP1  973 582-101  [HIRSCHMANN_973 582-101]  (value not drawn)
JP2  973 582-100  [HIRSCHMANN_973 582-100]  (value not drawn)
R39  ValueDisplayed: 0  [1206]  (hidden comment: MCR18EZHJ000)
R40  ValueDisplayed: 1.0k  [0402]  (hidden comment: CRCW04021K00JNED)
R41  ValueDisplayed: 0  [1206]  (hidden comment: MCR18EZHJ000)
T1  SRF0905-472Y  [SRF0905]  (value not drawn)
U3  TPS7A4533DCQR  [DCQ0006A_N]
U6  TPD1E10B06DPYT  [DPY0002A]  (value not drawn)
U9  TPD1E10B06DPYT  [DPY0002A]  (value not drawn)
U13  TPD1E10B06DPYT  [DPY0002A]  (value not drawn)
U16  TPD1E10B06DPYT  [DPY0002A]  (value not drawn)

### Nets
GND: C12.2 C13.2 C14.2 C15.2 D22.1(CATHODE) J1.1 J1.2 J1.7 J1.8 J1.19 J1.20 R41.2 T1.3 U3.3(GND) U3.6(GND) U6.1(K) U9.1(K) U13.1(K) U16.1(K)
VCC_3V3: C15.1 J1.4 J1.5 R40.2 U3.4(OUT) U3.5(SENSE)
VCC_IN: C11.2 D21.2 JP1.1 JP1.2 R39.1 T1.1
RXD: J1.13 U6.2(A)
SBWTCK: J1.12 U13.2(A)
SBWTDIO: J1.11 U16.2(A)
TXD: J1.14 U9.2(A)
NetC11_1: C11.1 D21.1 JP2.1 JP2.2 R41.1 T1.2
NetC12_1: C12.1 C13.1 C14.1 R39.2 T1.4 U3.1(~{SHDN}) U3.2(IN)
NetD22_2: D22.2(ANODE) R40.1

Not connected (* = marked no-connect by the designer): J1 3* 6* 9* 10* 15* 16* 17* 18*

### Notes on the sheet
- 20VDC to 3V3DC Power Supply
- Debug Port

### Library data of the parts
C11 = CMP-0008489-2: CAP, CERM, 0.1 uF, 100 V, +/- 20%, X7R, 1206; Manufacturer: AVX; TaMin_C: -55°C; ESR_ohm: 0.037; Polarized: N; SizeAreaWB_mm2: 10.92; Value1: 0.037 ohm; U/M: EA; Value: 0.1uF; TaMax_C: 125°C; SizeZ_mm: 1.35; SizeX_mm: 3.2; SizeY_mm: 1.6; Value2: 100V; SizeArea_mm2: 5.12; CompType: Capacitor; Cap_F: 100nF; AEC Category: Q200
C12 = CMP-0008509-2: CAP, CERM, 1 uF, 25 V, +/- 10%, X7R, 1206; Manufacturer: AVX; TaMin_C: -55°C; ESR_ohm: 0.013; Polarized: N; SizeAreaWB_mm2: 10.92; Value1: 0.013 ohm; U/M: EA; Value: 1uF; TaMax_C: 125°C; SizeZ_mm: 1.35; SizeX_mm: 3.2; SizeY_mm: 1.6; Value2: 25V; SizeArea_mm2: 5.12; CompType: Capacitor; Cap_F: 1µF; AEC Category: Q200
C13 C15 = CMP-0007987-2: CAP, CERM, 10 uF, 25 V, +/- 10%, X5R, 0805; Manufacturer: Samsung Electro-Mechanics; TaMin_C: -55°C; Polarized: N; SizeAreaWB_mm2: 6.75; Value1: Unknown; U/M: EA; Value: 10uF; TaMax_C: 85°C; SizeZ_mm: 1.45; SizeX_mm: 2; SizeY_mm: 1.25; Cap_Case: 0805; Value2: 25V; SizeArea_mm2: 2.5; Cap_F: 10µF; AEC Category: Q200
C14 = CMP-0007567-2: CAP, CERM, 0.1 uF, 25 V, +/- 10%, X7R, 0805; Manufacturer: AVX; TaMin_C: -55°C; ESR_ohm: 2.8d; Polarized: N; SizeAreaWB_mm2: 6.75; Value1: 0.28 ohm; U/M: EA; Value: 0.1uF; TaMax_C: 125°C; SizeZ_mm: 1.45; SizeX_mm: 2; SizeY_mm: 1.25; Cap_Case: 0805; Value2: 25V; SizeArea_mm2: 2.5; CompType: Capacitor; Cap_F: 100nF; AEC Category: Q200
D21 = CMP-0006059-3: Diode, TVS, Bi, 15 V, SOD323, 2-Leads, Body 1.9x1.45mm, No Polarity Mark; Manufacturer: Bourns; Value: 15V; AEC Category: Q101; Value1: 400W
D22 = CMP-0086387-1: as D1 on sheet MCU073A_CAPTIVATE-EMC_MCU
J1 = CMP-0054680-1: Receptacle, 2.54mm, 10x2, Gold, R/A, TH; Manufacturer: Sullins Connector Solutions; CNHeader: FALSE; Current_A: 3A; Gender: Female; Voltage_V: 250V; CompType: Socket Strip; Row_Count: 2; RowSpacing_mm: 2.54; CT: TRUE; Cert_UL: Y
JP1 = CMP-0055403-2: TEST SOCKET, PCB, 4MM, RED; Manufacturer: Hirschmann; CT: TRUE; CompType: Banana Jack; CNHeader: FALSE
JP2 = CMP-0055402-3: TEST SOCKET, PCB, 4MM, BLACK; Manufacturer: Hirschmann; CT: TRUE; CompType: Banana Jack; CNHeader: FALSE
R39 R41 = CMP-0018756-2: RES, 0, 5%, 0.25 W, 1206; Manufacturer: Rohm; Power_W: 250mW; TempCo: 200 ppm/C; Value_Code: 0000; U/M: EA; Value: 0; EIA_Code: E24; SizeX_mm: 3.2; SizeY_mm: 1.6; SizeZ_mm: 1.35; Value2: 0.25W; SizeArea_mm2: 5.12; VDC_V: 200V; AEC Category: Q200
R40 = CMP-0026852-3: as R17 on sheet MCU073A_CAPTIVATE-EMC_MCU
T1 = CMP-0030123-1: Line Filter; Manufacturer: Bourns; LeakageInd_H: 360nH; Value: 4.7mH; Lp: 4700; CompType: Transformer
U3 = CMP-0036723-1: Single Output Fast Transient Response LDO, 1.5 A, Fixed 3.3 V Output, 2.1 to 20 V Input, 6-pin SOT-223 (DCQ), -40 to 125 degC, Green (RoHS & no Sb/Br); Manufacturer: Texas Instruments; Vin(Min)(V): 2.1; Vout Adj(Max)(V): 3.3; Accuracy(%): 1; Vin(Max)(V): 20; SubFamily: Single Channel LDO; Iout(Max)(A): 1.5; Vdo(Typ)(mV): 300
U6 U9 U13 U16 = CMP-0043094-3: Single-Channel ESD in 0402 Package With 10pF Capacitance and 6V Breakdown, DPY0002A (X1SON-2); Alternate Manufacturer: Texas Instruments; Alternate PartNumber: TPD1E10B06DPYR; Breakdown Voltage(Min)(V): 6; SizeArea_mm2: 0.6; CompType: IC; SizeX_mm: 1.0; SizeZ_mm: 0.45; Rating: Catalog; SizeAreaWB_mm2: 3.2; AEC Category: Q200; IEC 61000-4-2 Air-Gap(+/- kV): 30; IO Capacitance(Typ)(pF): 10; AEC Qualified: N; Eco-Plan: TBD

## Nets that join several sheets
GND: MCU073A_CAPTIVATE-EMC_MCU (45 pins), MCU073A_CAPTIVATE-EMC_PowerSupply (19 pins)
VCC_3V3: MCU073A_CAPTIVATE-EMC_MCU (11 pins), MCU073A_CAPTIVATE-EMC_PowerSupply (6 pins)
RXD: MCU073A_CAPTIVATE-EMC_MCU (U1.4), MCU073A_CAPTIVATE-EMC_PowerSupply (J1.13 U6.2)
SBWTCK: MCU073A_CAPTIVATE-EMC_MCU (U1.2), MCU073A_CAPTIVATE-EMC_PowerSupply (J1.12 U13.2)
SBWTDIO: MCU073A_CAPTIVATE-EMC_MCU (C9.2 R15.1 U1.1), MCU073A_CAPTIVATE-EMC_PowerSupply (J1.11 U16.2)
TXD: MCU073A_CAPTIVATE-EMC_MCU (U1.3), MCU073A_CAPTIVATE-EMC_PowerSupply (J1.14 U9.2)

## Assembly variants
001: not fitted FID1 FID2 FID3 R39 R41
